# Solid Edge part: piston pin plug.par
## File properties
Author: Vicky Raina
Template: Normal.par
Last saved by: Robert a Rhodes jr
Revision: 2
Application: Solid Edge
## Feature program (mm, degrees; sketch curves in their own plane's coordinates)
sketch for "unnamed Protrusion 1" plane through (0, 0, 0) normal (0, 0, 1) x-axis (1, 0, 0)
  circle centre (0, 0) radius 5.5
extrude "unnamed Protrusion 1" add finite 12 along -normal
sketch for "unnamed Protrusion 2" plane through (0, 0, 0) normal (0, 0, 1) x-axis (0, 1, 0)
  circle centre (0, 0) radius 11
extrude "unnamed Protrusion 2" add finite 3 along +normal
fillet "unnamed Round 1"
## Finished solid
Body 1: solid body, 6 faces, 5 edges, 0 vertices.
  Faces by surface: plane 3, cylinder 2, torus 1
  Edges by curve: circle 5
Bounding box of the edges (mm; curved faces can reach further): 22.000 x 22.000 x 15.000, from (-11, -11, -12) to (11, 11, 3).
Cylindrical faces by radius (mm): R5.5 x1, R11 x1
Toroidal faces (ring radius, tube radius in mm): R9 r2 x1
Planar faces by outward normal: +z 1, -z 2
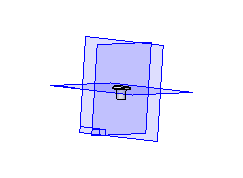
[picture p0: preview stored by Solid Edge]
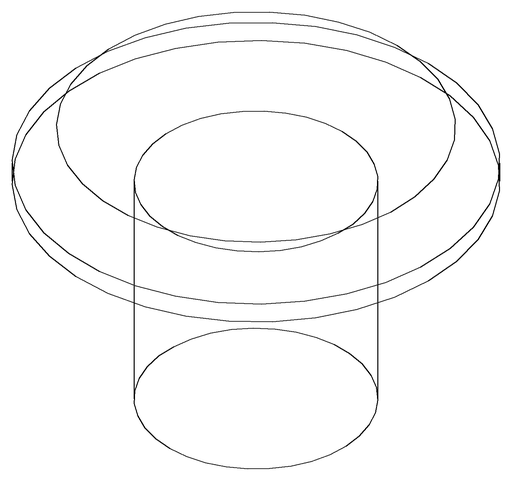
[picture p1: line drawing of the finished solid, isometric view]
